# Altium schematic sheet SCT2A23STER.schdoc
size 127 x 101 mm
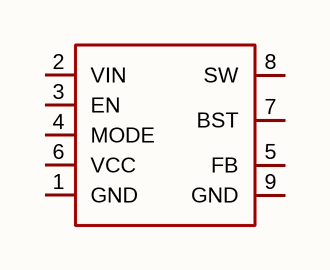
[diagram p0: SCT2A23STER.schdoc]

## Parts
U?  sct2a23ster  [ESOP-8_L4.9-W3.9-P1.27-LS6.0-BL-EP-1]  (value not drawn)

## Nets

Not connected (* = marked no-connect by the designer): U? 1(GND) 2(VIN) 3(EN) 4(MODE) 5(FB) 6(VCC) 7(BST) 8(SW) 9(GND)

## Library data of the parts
U? = sct2a23ster: 功能类型:降压型;工作电压:4.5V~100V;输出电压:1.2V~30V;输出电流:1.2A;输出类型:可调;; Manufacturer: SCT(芯洲科技); AddInBom: yes; ModelId: 1edf17d9e1eb44b9aabe355eb95382d1; ModelTransform: 192.913,236.22,0,0,0,0,0,0,0; Function: 降压型; Output Current: 1.2A; Frequency - Switching: 300kHz; Synchronous Rectifier: 是; Number of Outputs: 1; Topology: 降压式; Quiescent Current: 15uA; Switch tube (built-in/external): 内置; Output Type: 可调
